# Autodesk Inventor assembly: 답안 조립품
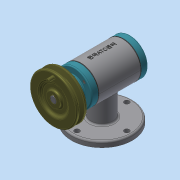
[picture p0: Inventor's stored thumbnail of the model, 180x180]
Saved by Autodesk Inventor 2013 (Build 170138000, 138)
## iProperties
Created: 2018-11
Part Number: 답안 조립품
Document SubType Name: Assembly
Designer: dgall
Mass: 1457.2 g
Surface Area: 1425.7 cm^2
Volume: 459.811 cm^3
Density: 3.16913 g/cm^3
Author: dgall
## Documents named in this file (18)
- C:\Users\dgall\Desktop\381107V1027\답안 조립품.iam
- C:\Users\dgall\Desktop\381107V1027\본체.ipt
- C:\Users\dgall\Desktop\381107V1027\V-벨트풀리.ipt
- C:\Users\dgall\Desktop\381107V1027\가변스프링.ipt
- C:\Users\dgall\Desktop\381107V1027\뒤커버.ipt
- C:\Users\dgall\Desktop\381107V1027\멈춤나사 M3x8.ipt
- C:\Users\dgall\Desktop\381107V1027\베어링 6201.ipt
- C:\Users\dgall\Desktop\381107V1027\베어링 6202.ipt
- C:\Users\dgall\Desktop\381107V1027\본체커버.ipt
- C:\Users\dgall\Desktop\381107V1027\슬라이드.ipt
- C:\Users\dgall\Desktop\381107V1027\앞커버.ipt
- C:\Users\dgall\Desktop\381107V1027\오일 실 12 22 7.ipt
- 오일 실 12 22 7.ipt
- C:\Users\dgall\Desktop\381107V1027\키 4x4x18.ipt
- 키 4x4x18.ipt
- C:\Users\dgall\Desktop\381107V1027\편심축.ipt
- C:\Users\dgall\Desktop\381107V1027\개스킷.ipt
- C:\Users\dgall\Desktop\381107V1027\볼트 M3x0.5x8.ipt
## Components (4 placed, 3 different names)
1. V-벨트풀리:1 — 플러쉬:1
2. 가변스프링:1
3. 개스킷:1
4. 개스킷:2
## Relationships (1: Flush 1)
- 플러쉬:1 [Flush]: V-벨트풀리:1
